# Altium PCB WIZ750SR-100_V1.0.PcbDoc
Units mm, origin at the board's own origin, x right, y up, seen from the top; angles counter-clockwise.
Board outline 50 x 30 mm, 4 copper layers (Top Layer, Internal Plane 1, Internal Plane 2, Bottom Layer); 73 components, 80 nets, 307 pads, 130 vias.
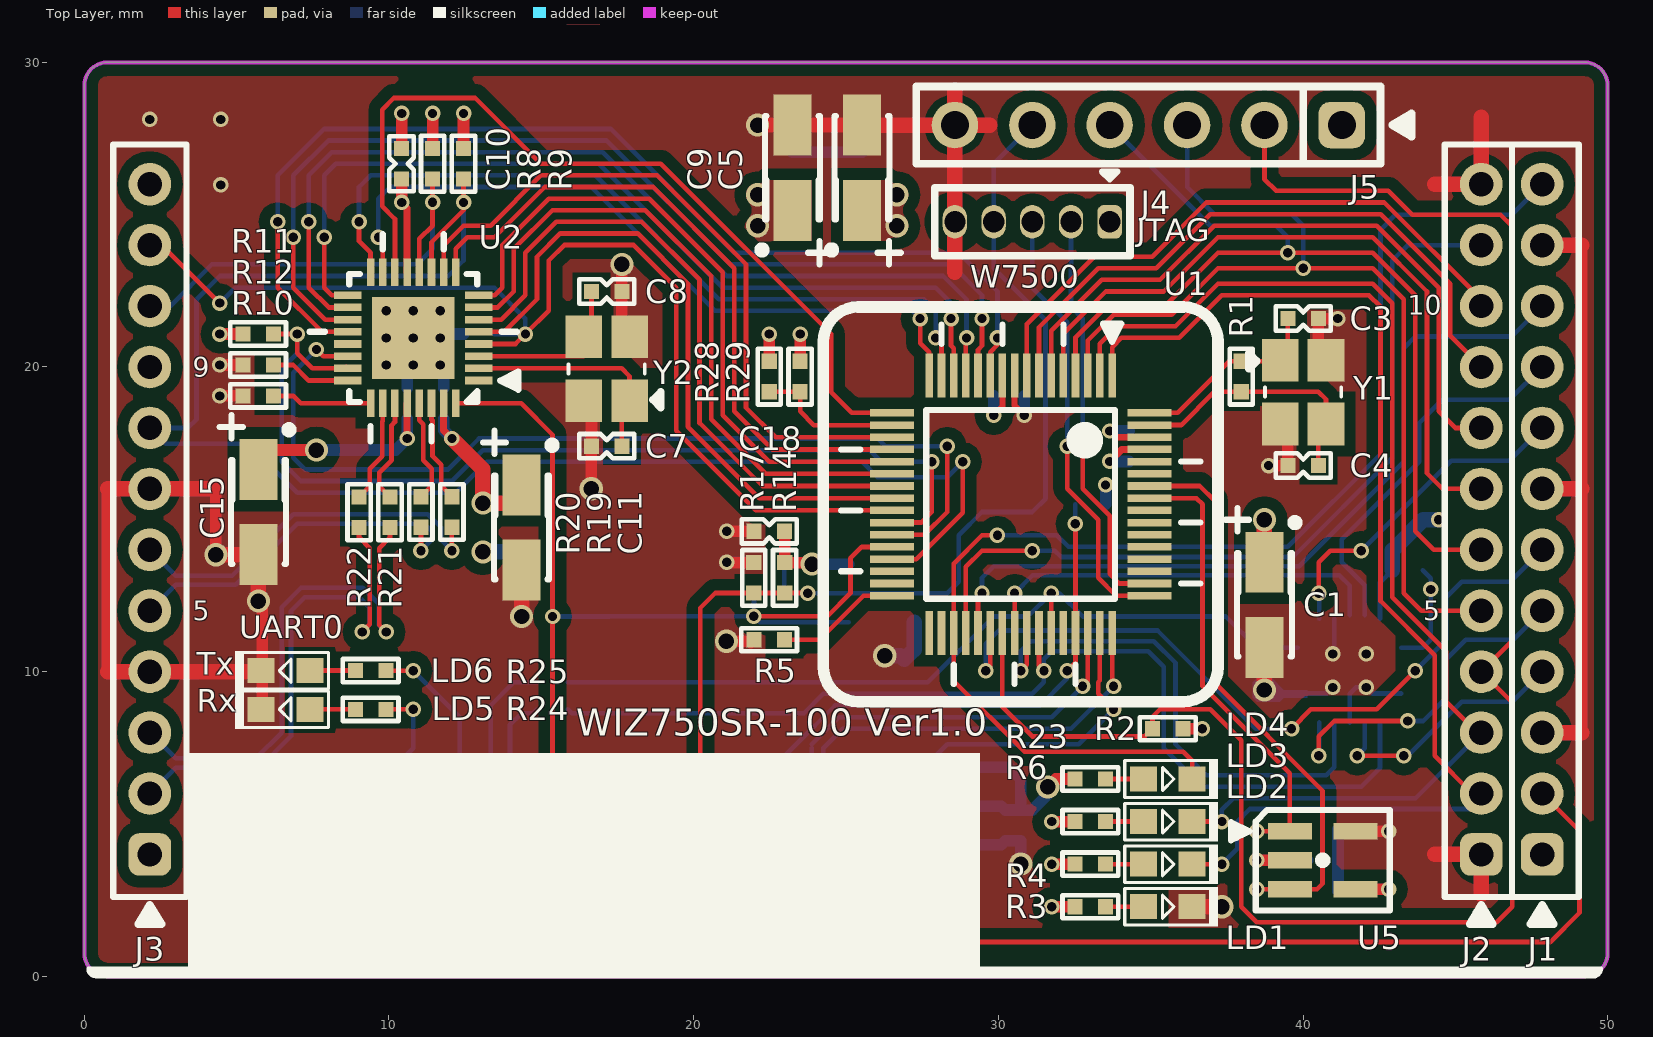
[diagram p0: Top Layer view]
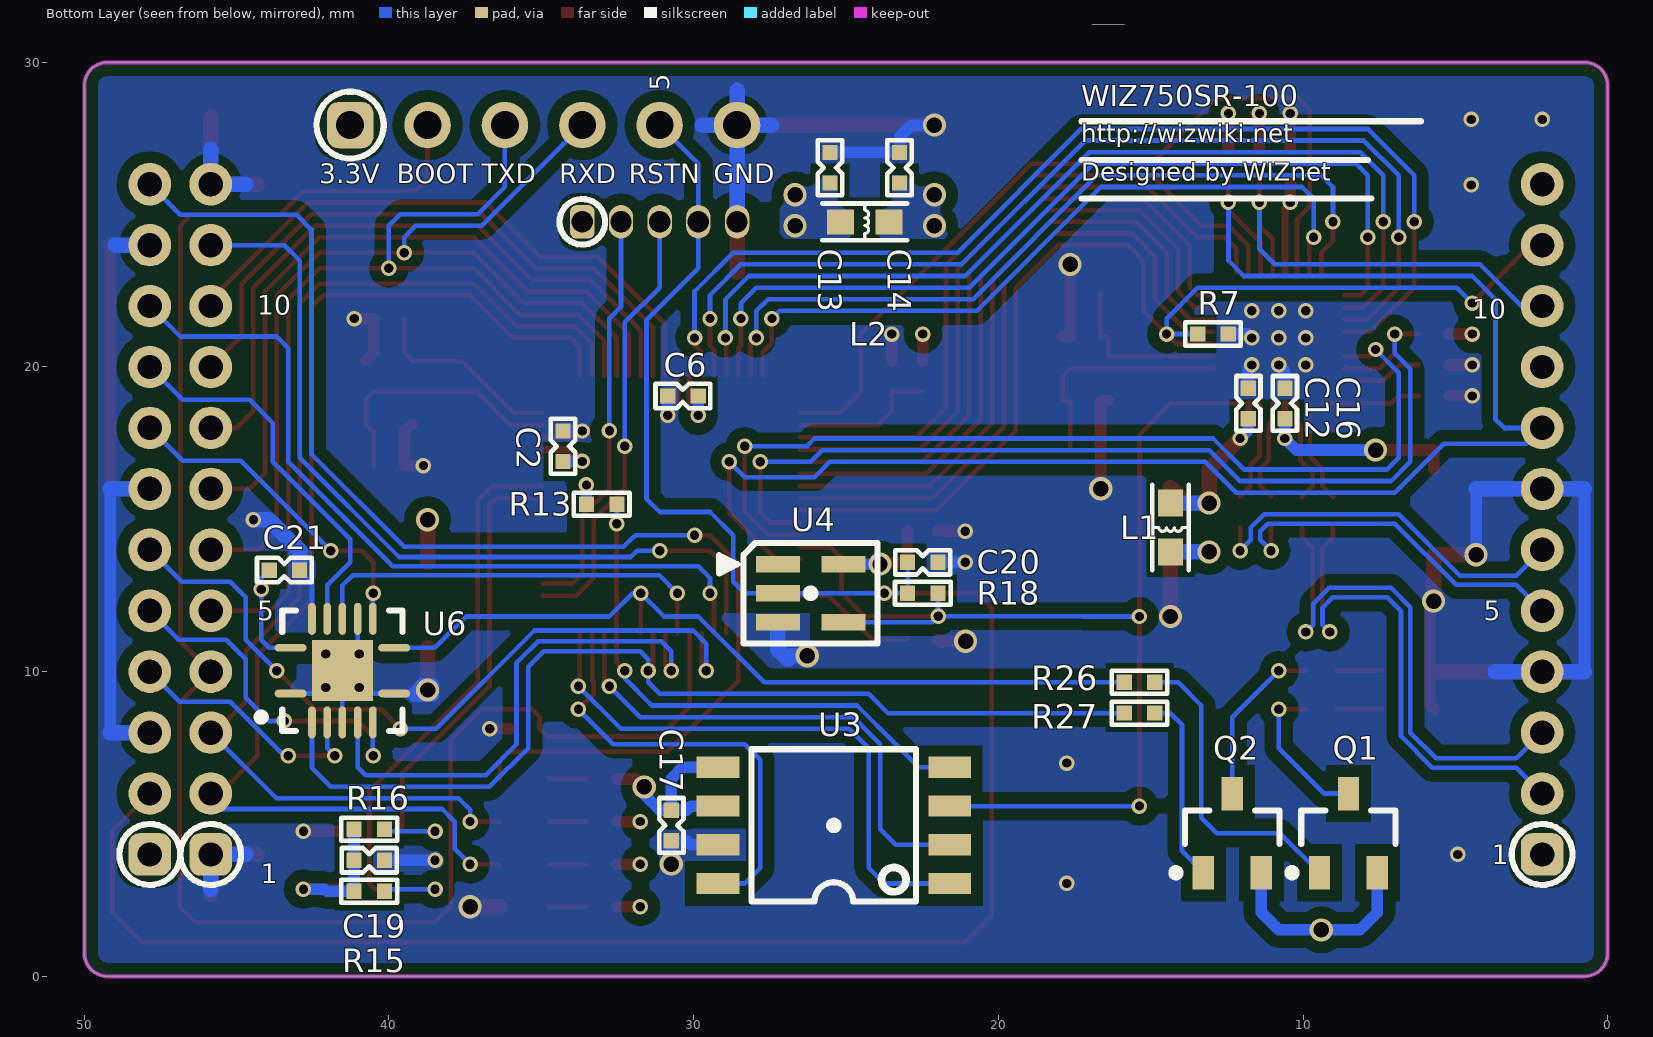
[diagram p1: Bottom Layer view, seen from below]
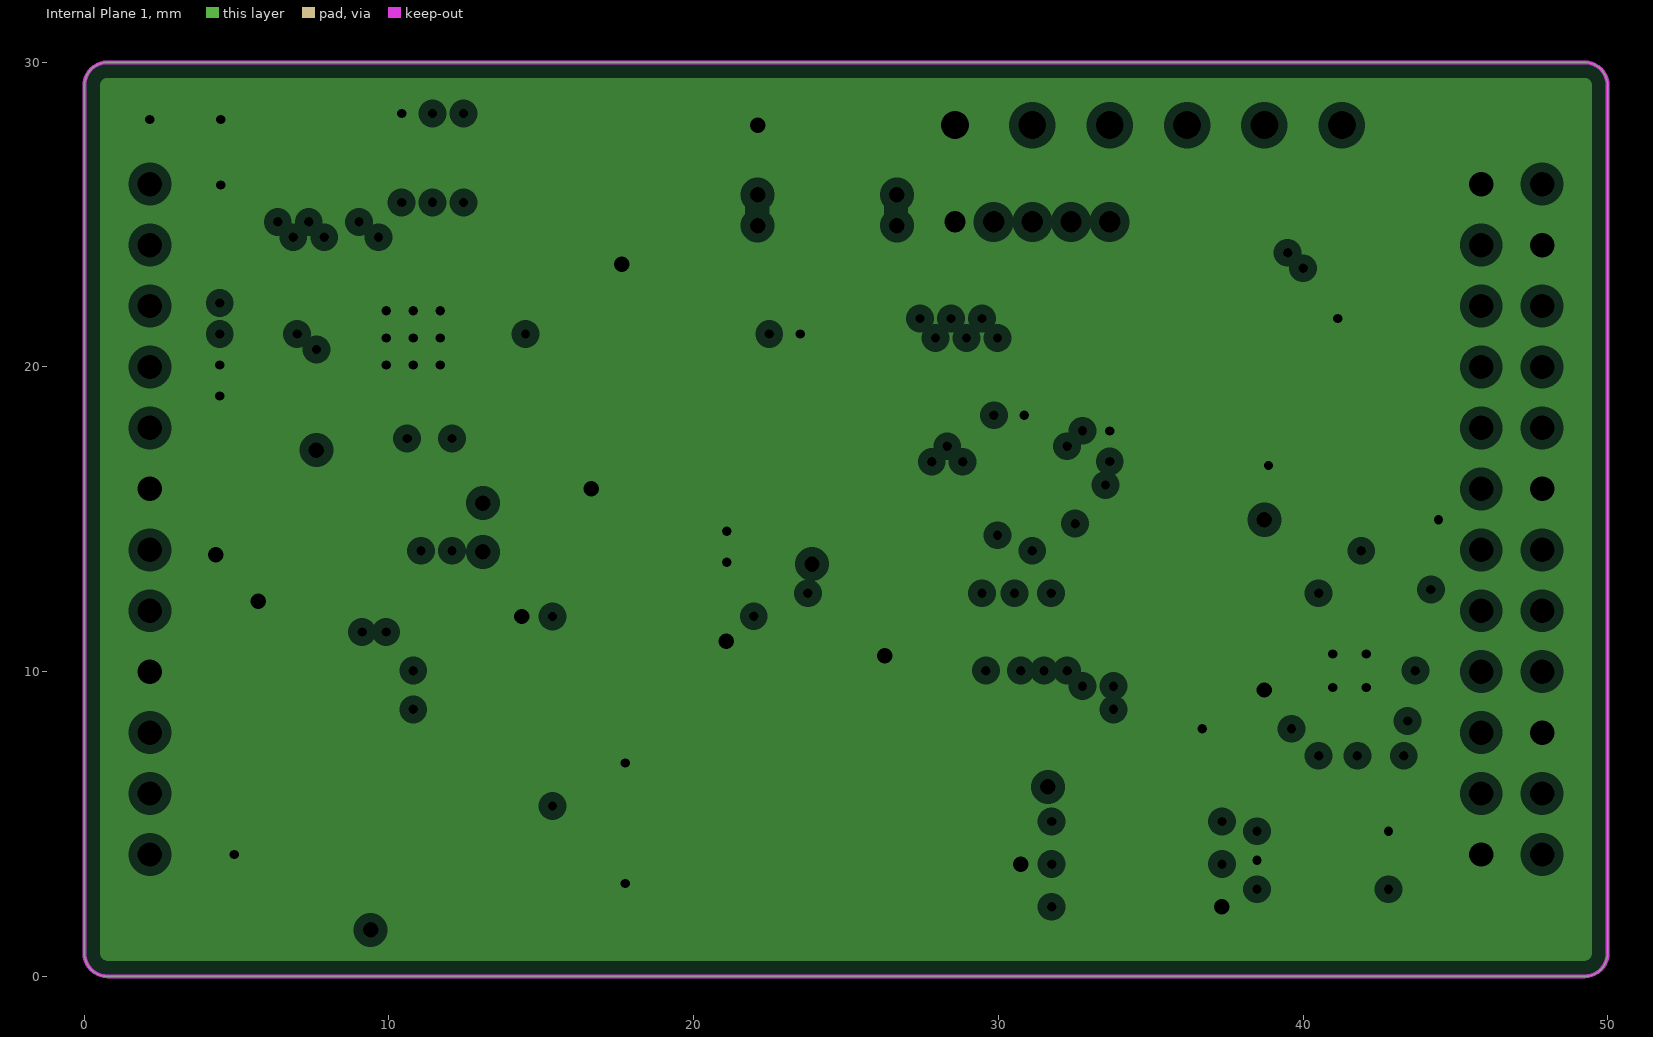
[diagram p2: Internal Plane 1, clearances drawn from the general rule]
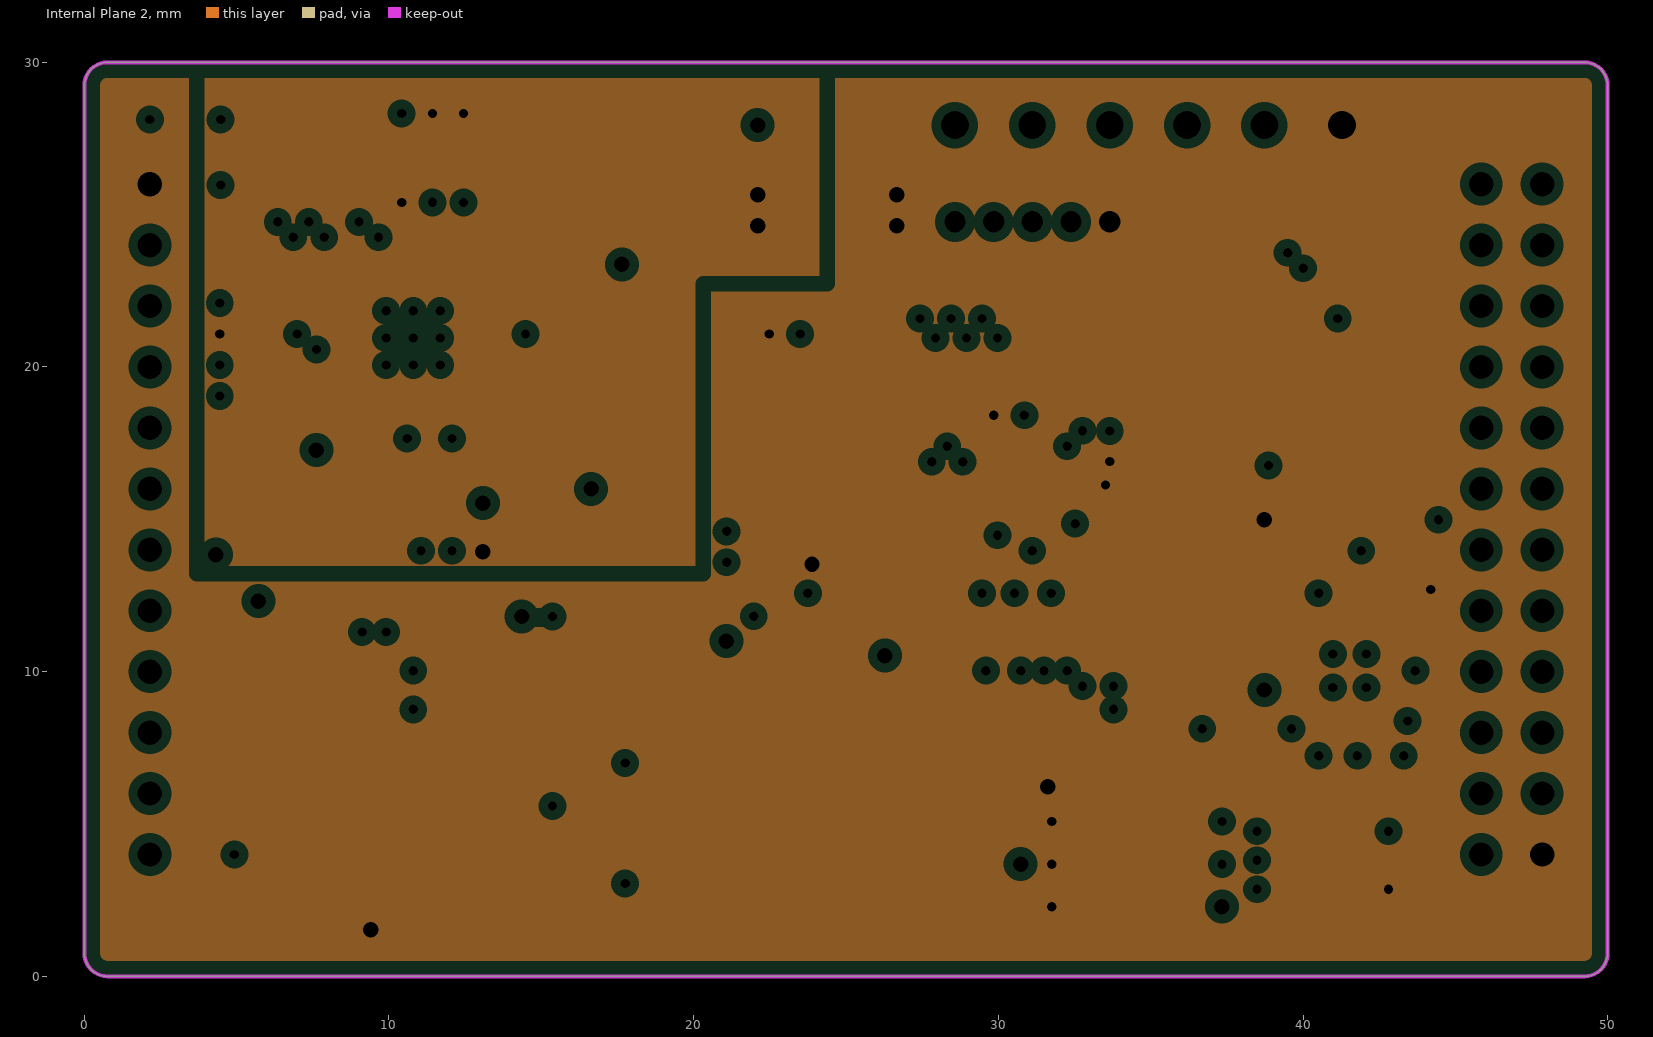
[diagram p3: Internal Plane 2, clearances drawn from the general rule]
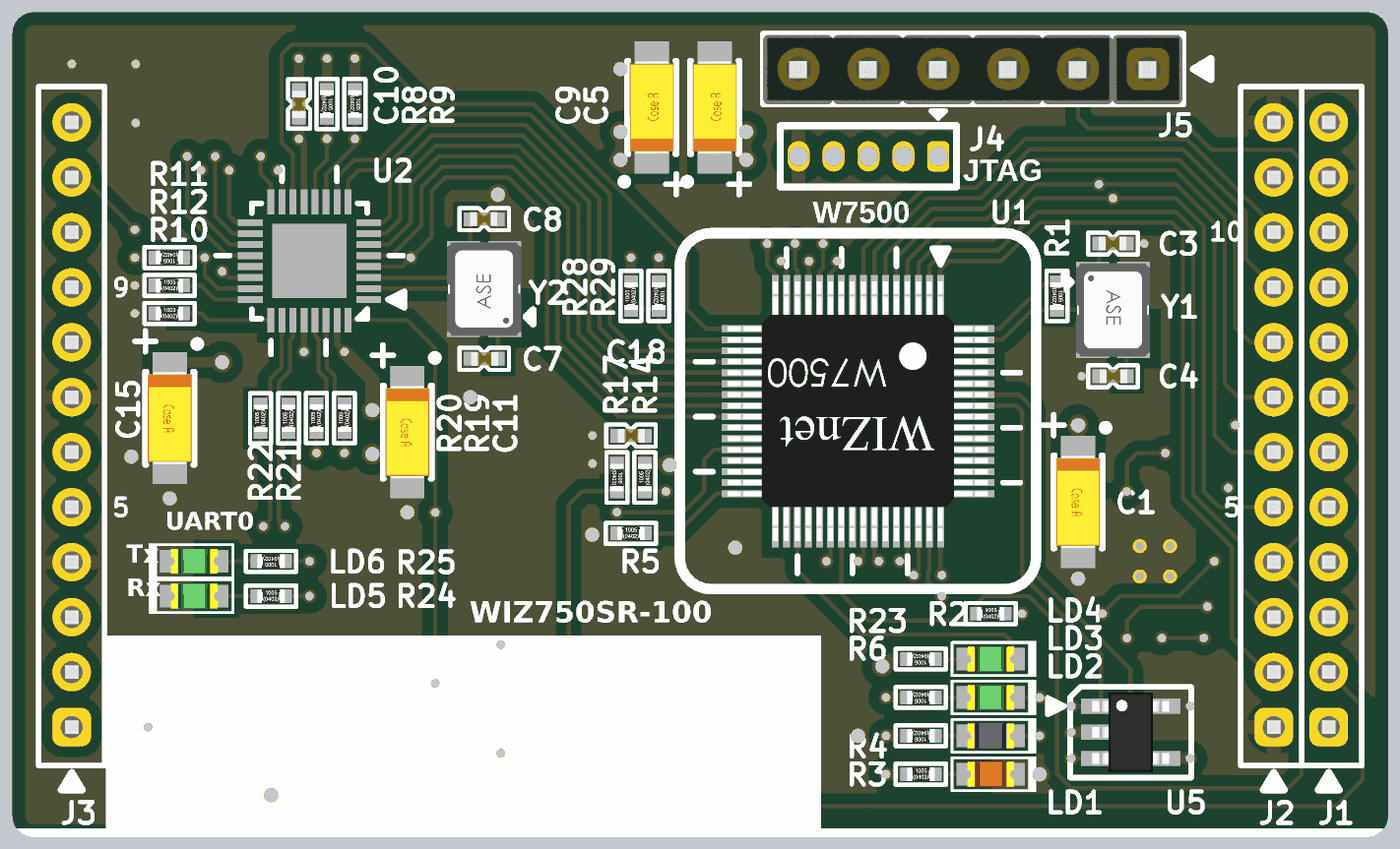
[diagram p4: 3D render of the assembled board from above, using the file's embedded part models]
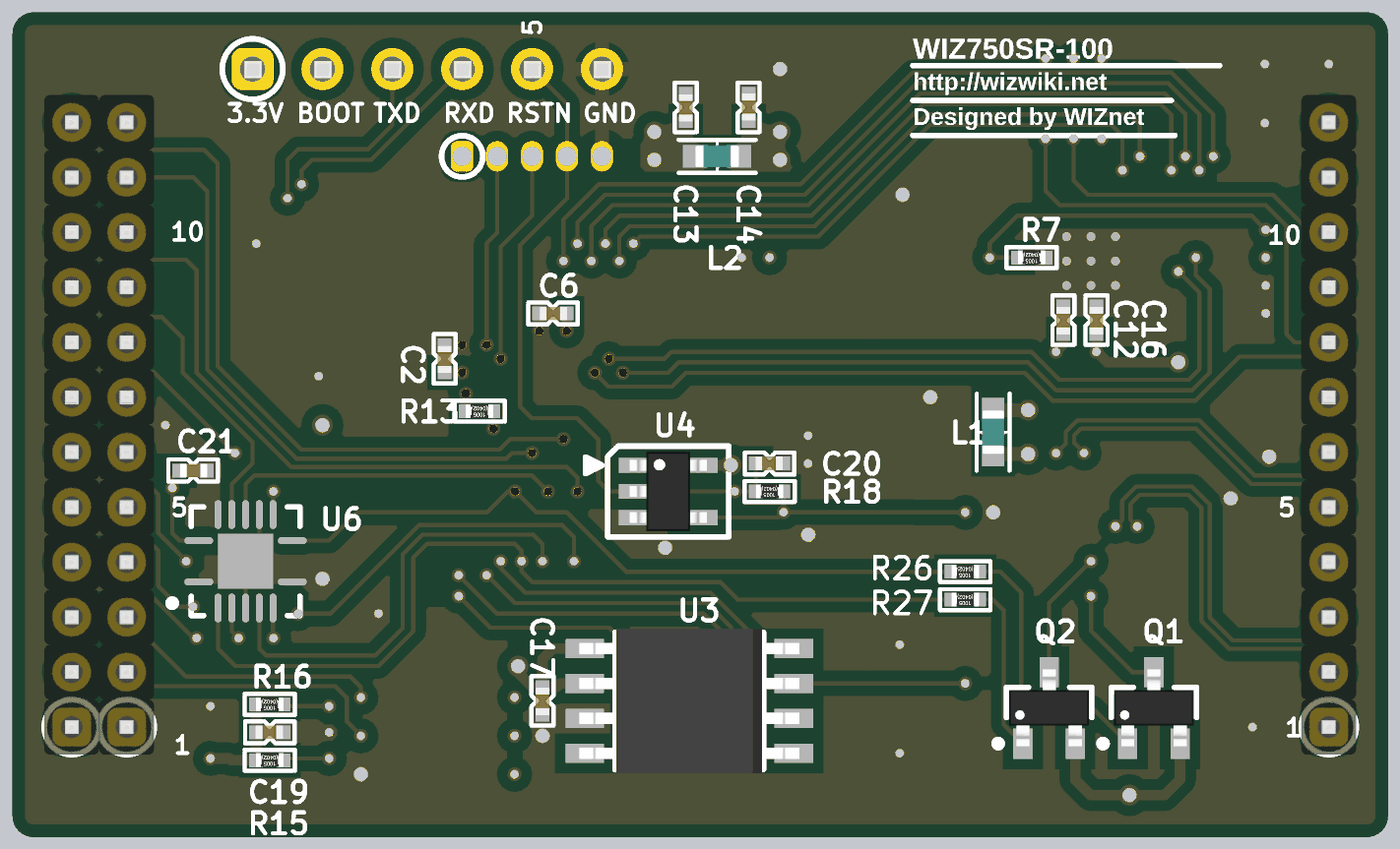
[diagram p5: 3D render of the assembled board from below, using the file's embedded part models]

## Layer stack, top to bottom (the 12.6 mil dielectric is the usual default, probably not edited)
Top Solder: solder mask 0.0102, Solder Resist, Dk 3.5
Top Layer: signal copper 0.0356
Dielectric1: core 0.32, FR-4, Dk 4.8
Internal Plane 1: plane copper 0.0356, net GND
Dielectric5: prepreg 0.32, FR-4, Dk 4.8
Internal Plane 2: plane copper 0.0356, net (Multiple Nets)
Dielectric6: core 0.32, FR-4, Dk 4.8
Bottom Layer: signal copper 0.0356
Bottom Solder: solder mask 0.0102, Solder Resist, Dk 3.5

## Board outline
0,0.762 0,29.238 cw(c0.762,29.238) 0.762,30 49.238,30 cw(c49.238,29.238) 50,29.238 50,0.762 cw(c49.238,0.762) 49.238,0 0.762,0 cw(c0.762,0.762)

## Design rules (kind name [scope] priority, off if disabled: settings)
Clearance [All] p1: gap=0.15 except(0.381: Arc-Poly Track-Poly SMDPad-Poly THPad-Poly Via-Poly Fill-Poly Poly-Poly Poly-Region)
DiffPairsRouting [All] p1: maxlimit=0.152 minlimit=0.152 mostfreqgap=0.152 toplayer_minwidth=0.152 toplayer_maxwidth=0.152 toplayer_prefwidth=0.152 bottomlayer_minwidth=0.152 bottomlayer_maxwidth=0.152 bottomlayer_prefwidth=0.152 maxuncoupledlength=15.24
HoleSize [All] p1: absolutevalues=TRUE maxlimit=4.064 minlimit=0.025 maxpercent=80.000 minpercent=20.000
PlaneClearance [All] p1: clearance=0.305
PlaneConnect [All] p1: planeconnectstyle=Direct reliefexpansion=0.508 reliefentries=4 reliefconductorwidth=0.254 reliefairgap=0.254
PolygonConnect PolygonConnect_2 [IsPad vs IsNamedPolygon('Top Layer-GND') Or  IsNamedPolygon('Bottom Layer-GND')] p1: connectstyle=Relief reliefconductorwidth=0.381 reliefentries=4 polygonreliefangle="90 Angle" airgapwidth=0.381
PolygonConnect PolygonConnect_1 [IsVia] p2: connectstyle=Direct reliefconductorwidth=0.254 reliefentries=4 polygonreliefangle="90 Angle" airgapwidth=0.254
PolygonConnect [All] p3: connectstyle=Direct reliefconductorwidth=0.254 reliefentries=4 polygonreliefangle="90 Angle" airgapwidth=0.254
RoutingVias [All] p1: holewidth=0.305 width=0.508 viastyle="Through Hole" minholewidth=0.305 minwidth=0.508 maxholewidth=0.508 maxwidth=0.762
SolderMaskExpansion [All] p1: expansion=0
Width [All] p1: maxlimit=0.508 minlimit=0.102 preferedwidth=0.152 minimp=50.000000 maximp=50.000000 favimp=50.000000
26 further rules are at their usual default settings.

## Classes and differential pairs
component class 2.WIZ750SR_Transceiver: LD1 LD2 R41
component class 1.WIZ750JR_W7500_: C1 C2 C3 C4 C5 C6 LD1 LD2 LD3 LD4 LD5 LD6 Q1 Q2 R1 R2 R3 R4 R5 R6 R23 R24 R25 R26 R27 R28 R29 U1 Y1
differential pair MDI0_T: +MDI0_T_P -MDI0_T_N
differential pair MDI0_R: +MDI0_R_P -MDI0_R_N
differential pair MDI0_R: +MDI_R_P -MDI_R_N
differential pair MDI0_T: +MDI_T_P -MDI_T_N

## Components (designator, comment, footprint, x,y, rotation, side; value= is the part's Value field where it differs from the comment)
C1 "10uF/16V" "CAP-A Size" 38.735,12.192 r270 top
C2 "1uF" CAP-0402#1 34.29,17.399 r270 bottom
C3 "30pF" CAP-0402#1 40.005,21.59 r180 top
C4 "30pF" CAP-0402#1 40.005,16.764 r0 top
C5 "10uF/16V" "CAP-A Size" 25.527,26.543 r90 top
C6 "1uF" CAP-0402#1 30.353,19.05 r180 bottom
C7 "27pF" CAP-0402#1 17.145,17.399 r0 top
C8 "27pF" CAP-0402#1 17.145,22.479 r180 top
C9 "10uF/16V" "CAP-A Size" 23.241,26.543 r90 top
C10 "0.1uF" CAP-0402#1 10.414,26.67 r270 top
C11 "10uF/16V" "CAP-A Size" 14.351,14.732 r270 top
C12 "0.1uF" CAP-0402#1 11.795,18.805 r270 bottom
C13 "0.1uF" CAP-0402#1 25.527,26.543 r270 bottom
C14 "0.1uF" CAP-0402#1 23.241,26.543 r90 bottom
C15 "10uF/16V" "CAP-A Size" 5.715,15.24 r270 top
C16 "0.1uF" CAP-0402#1 10.595,18.805 r270 bottom
C17 "0.1uF(NM)" CAP-0402#1 30.734,4.953 r270 bottom
C18 "0.1uF" CAP-0402#1 22.479,14.605 r0 top
C19 "0.1uF(NM)" CAP-0402#1 40.648,3.81 r0 bottom
C20 "0.1uF" CAP-0402#1 22.479,13.589 r0 bottom
C21 "0.1uF" CAP-0402#2 43.434,13.335 r180 bottom
J1 "2.00mm 1x12 Pin" IDC-1X12(2MM) 47.85,4 r90 top locked
J2 "2.00mm 1x12 Pin(NM)" IDC-1X12(2MM) 45.85,4 r90 top locked
J3 "2.00mm 1x12 Pin" IDC-1X12(2MM) 2.15,4 r90 top locked
J4 "1.27mm_1x5_Pin_header_DIP(NM)" IDC-1X5(1.27MM) 33.655,24.765 r180 top
J5 "2.54mm 1x6 Pin Header DIP(NM)" IDC-1X6 41.275,27.94 r180 top locked
L1 "HH-1M1608-121JT" IND-0603 14.351,14.732 r270 bottom
L2 "HH-1M1608-121JT" IND-0603 24.384,24.765 r180 bottom
LD1 "RED-0603" LED-0603-RED 35.56,2.286 r0 top
LD2 "BLUE-0603" LED-0603-BLUE 35.56,3.683 r0 top
LD3 "GREEN-0603" LED-0603-GREEN 35.56,5.08 r0 top
LD4 "GREEN-0603" LED-0603-GREEN 35.56,6.477 r0 top
LD5 "GREEN-0603" LED-0603-GREEN 6.604,8.763 r180 top
LD6 "GREEN-0603" LED-0603-GREEN 6.604,10.033 r180 top
Q1 "Q-MMBT4403" Q-MMBT4403-SOT23 8.509,4.699 r90 bottom
Q2 "Q-MMBT4403" Q-MMBT4403-SOT23 12.319,4.699 r90 bottom
R1 "1M" RES-0402#1 37.973,19.685 r270 top
R2 "4.7K" RES-0402#1 35.56,8.128 r0 top
R3 "330R" RES-0402#1 33.02,2.286 r0 top
R4 "1K" RES-0402#1 33.02,3.683 r180 top
R5 "4.7K" RES-0402#1 22.479,11.049 r0 top
R6 "330R" RES-0402#1 33.02,5.08 r180 top
R7 "5.1K" RES-0402#1 12.954,21.082 r0 bottom
R8 "5.1K" RES-0402#1 11.43,26.67 r270 top
R9 "5.1K" RES-0402#1 12.446,26.67 r270 top
R10 "6.19K / 1%" RES-0402#1 5.707,19.05 r0 top
R11 "5.1K" RES-0402#1 5.707,21.082 r180 top
R12 "5.1K" RES-0402#1 5.707,20.066 r0 top
R13 "4.7K(NM)" RES-0402#1 33.02,15.494 r0 bottom
R14 "4.7K(NM)" RES-0402#1 22.987,13.081 r90 top
R15 "4.7K(NM)" RES-0402#1 40.648,2.794 r0 bottom
R16 "4.7K(NM)" RES-0402#1 40.648,4.826 r0 bottom
R17 "4.7K" RES-0402#1 21.971,13.081 r270 top
R18 "0R(NM)" RES-0402#1 22.479,12.573 r0 bottom
R19 "3.3R" RES-0402#1 12.065,15.24 r90 top
R20 "3.3R" RES-0402#1 11.049,15.24 r90 top
R21 "3.3R" RES-0402#1 10.033,15.232 r90 top
R22 "3.3R" RES-0402#1 9.017,15.232 r90 top
R23 "330R" RES-0402#1 33.02,6.477 r180 top
R24 "330R" RES-0402#2 9.398,8.763 r0 top
R25 "330R" RES-0402#2 9.398,10.033 r180 top
R26 "1K" RES-0402#2 15.367,9.652 r0 bottom
R27 "1K" RES-0402#2 15.367,8.636 r0 bottom
R28 "4.7K/NC" RES-0402#2 22.479,19.685 r90 top
R29 "4.7K" RES-0402#2 23.495,19.685 r270 top
U1 "W7500" W7500-LQFP64 30.734,15.494 r270 top locked
U2 "IP101GR/GRI" QFN32(0.4/4X4) 10.795,20.955 r180 top locked
U3 "AT45DB161E-SHF-T" SO-08-EIAJ 25.4,4.953 r0 bottom
U4 "SN74LVC1G04DBVR" SOT-23-5L 26.162,12.573 r180 bottom
U5 "24AA16T-I/OT" SOT-23-5L 40.648,3.81 r0 top
U6 "SN74LVC125A" SN74LVC125A 41.529,10.033 r180 bottom
Y1 "12MHz" OSC-TZ1067B 40.005,19.177 r270 top
Y2 "25MHz" OSC-82J0626 17.145,19.939 r90 top

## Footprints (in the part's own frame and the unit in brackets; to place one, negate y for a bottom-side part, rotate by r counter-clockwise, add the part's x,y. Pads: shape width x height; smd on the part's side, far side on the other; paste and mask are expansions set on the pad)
CAP-0402#1 [mm]
  rect 0.5x0.5 smd: 1(-0.5,0) 2(0.5,0)
  silkscreen extent -0.9,-0.4 0.9,0.4, body extent -0.48,-0.25 0.52,0.25, height 0.6
CAP-0402#2 [mm] "Ceramic CAP 0402(1005)"
  rect 0.5x0.5 smd: 1(-0.5,-0.004) 2(0.5,-0.004)
  silkscreen extent -0.9,-0.4 0.9,0.4, body extent -0.48,-0.25 0.52,0.25, height 0.6
"CAP-A Size" [mm] "Tantal CAP A Size EIA/IECQ 3216"
  rect 2x1.25 smd: 1(-1.4,0) 2(1.4,0)
  silkscreen extent -3.17,-1.27 1.7,1.12, body extent -1.7,-0.8 1.7,0.8, height 1.75
IDC-1X5(1.27MM) [mm]
  rrect50% 0.8x1.1 hole 0.7: 1(0,0)
  oval 0.8x1.1 hole 0.7: 2(1.27,0) 3(2.54,0) 4(3.81,0) 5(5.08,0)
  silkscreen extent -0.66,-1.65 5.74,1.11
IDC-1X6 [mil] "6-Way 2.54 mm Male Header"
  rrect50% 60x60 hole 36: 1(0,0)
  round 60 hole 36: 2(100,0) 3(200,0) 4(300,0) 5(400,0) 6(500,0)
  silkscreen extent -90,-50 550,50, body extent -49,-49 551,51, height 336
IDC-1X12(2MM) [mil]
  rrect50% 55x55 hole 31.5: 1(0,0)
  round 55 hole 31.5: 2(78.74,0) 3(157.48,0) 4(236.22,0) 5(314.96,0) 6(393.7,0) 7(472.44,0) 8(551.18,0) 9(629.92,0) 10(708.66,0) 11(787.4,0) 12(866.14,0)
  silkscreen extent -90,-47 917,39, body extent -39,-39 906,39, height 217
IND-0603 [mm] "Inductor 0603(1608)"
  rect 0.89x0.82 smd: 1(-0.8,0) 2(0.8,0)
  silkscreen extent -1.4,-0.6 1.4,0.6, body extent -0.8,-0.4 0.8,0.4, height 0.95
LED-0603-BLUE [mm] "LED-0603-BLUE"
  rect 0.89x0.82 smd: 1(-0.8,0) 2(0.8,0)
  silkscreen extent -1.41,-0.65 1.65,0.65, body extent -0.85,-0.45 0.85,0.45, height 0.9
LED-0603-GREEN [mm] "LED-0603-GREEN"
  rect 0.89x0.82 smd: 1(-0.8,0) 2(0.8,0)
  silkscreen extent -1.41,-0.65 1.65,0.65, body extent -0.85,-0.45 0.85,0.45, height 0.9
LED-0603-RED [mm] "LED-0603-RED"
  rect 0.89x0.82 smd: 1(-0.8,0) 2(0.8,0)
  silkscreen extent -1.41,-0.65 1.65,0.65, body extent -0.85,-0.45 0.85,0.45, height 0.9
OSC-82J0626 [mm]
  rect 1.4x1.2 smd: 1(-1.05,-0.75) 2(1.05,-0.75) 3(1.05,0.75) 4(-1.05,0.75)
  silkscreen extent -1.27,-1.78 0.15,1.25, body extent -1.7,-1.35 1.7,1.35, height 1.06
OSC-TZ1067B [mm]
  rect 1.4x1.2 smd: 1(-1.05,-0.75) 2(1.05,-0.75) 3(1.05,0.75) 4(-1.05,0.75)
  silkscreen extent -1.27,-1.78 0.15,1.25, body extent -1.7,-1.35 1.7,1.35, height 1.06
Q-MMBT4403-SOT23 [mm] "PNP General-Purpose Amplifier"
  rect 1.1x0.7 smd: 1(-1.3,0.95) 2(-1.3,-0.95) 3(1.3,0)
  silkscreen extent -1.42,-1.55 0.75,1.98, body extent -1.4,-1.45 1.4,1.45, height 1.3
QFN32(0.4/4X4) [mm]
  rect 0.9x0.25 smd: 1(-2.15,1.4) 2(-2.15,1) 3(-2.15,0.6) 4(-2.15,0.2) 5(-2.15,-0.2) 6(-2.15,-0.6) 7(-2.15,-1) 8(-2.15,-1.4) 17(2.15,-1.4) 18(2.15,-1) 19(2.15,-0.6) 20(2.15,-0.2) 21(2.15,0.2) 22(2.15,0.6) 23(2.15,1) 24(2.15,1.4)
  rect 0.25x0.9 smd: 9(-1.4,-2.15) 10(-1,-2.15) 11(-0.6,-2.15) 12(-0.2,-2.15) 13(0.2,-2.15) 14(0.6,-2.15) 15(1,-2.15) 16(1.4,-2.15) 25(1.4,2.15) 26(1,2.15) 27(0.6,2.15) 28(0.2,2.15) 29(-0.2,2.15) 30(-0.6,2.15) 31(-1,2.15) 32(-1.4,2.15)
  rect 2.7x2.7 smd: 33(0,0)
  silkscreen extent -3.45,-3.4 3.4,3.4, body extent -2.1,-2.1 2.1,2.1, height 0.76
RES-0402#1 [mm]
  rect 0.5x0.5 smd: 1(-0.5,0) 2(0.5,0)
  silkscreen extent -0.91,-0.38 0.91,0.38, body extent -0.5,-0.25 0.5,0.25, height 0.35
RES-0402#2 [mm]
  rect 0.5x0.5 smd: 1(-0.5,-0.004) 2(0.5,-0.004)
  silkscreen extent -0.91,-0.38 0.91,0.38, body extent -0.5,-0.25 0.5,0.25, height 0.35
SN74LVC125A [mm] "QFN, 14-Leads, Body 3.50x3.50mm, Pitch 0.50mm/1.50mm, Thermal Pad 2.00x2.00mm, IPC Low Density"
  oval 1.05x0.25 smd: 1(-1.7,-0.75) 7(1.7,-0.75) 8(1.7,0.75) 14(-1.7,0.75)
  oval 0.25x1.05 smd: 2(-1,-1.7) 3(-0.5,-1.7) 4(0,-1.7) 5(0.5,-1.7) 6(1,-1.7) 9(1,1.7) 10(0.5,1.7) 11(0,1.7) 12(-0.5,1.7) 13(-1,1.7)
  rect 2x2 smd: 15(0,0)
  silkscreen extent -2.79,-1.97 1.97,1.97, body extent -1.83,-1.83 1.83,1.83, height 1
SO-08-EIAJ [mm]
  rect 1.4x0.7 smd: 1(-3.8,1.905) 2(-3.8,0.635) 3(-3.8,-0.635) 4(-3.8,-1.905) 5(3.8,-1.905) 6(3.8,-0.635) 7(3.8,0.635) 8(3.8,1.905)
  silkscreen extent -2.7,-2.5 2.7,2.5, body extent -4,-2.63 4,2.63, height 2.58
SOT-23-5L [mm]
  rect 1.45x0.55 smd: 1(-1.075,0.95) 2(-1.075,0) 3(-1.075,-0.95) 4(1.075,-0.95) 5(1.075,0.95)
  silkscreen extent -3.01,-1.65 2.2,1.65, body extent -1.4,-1.45 1.4,1.45, height 1.45
W7500-LQFP64 [mm] "WIZnet ARM Cortex-M0, LQFP64, Pitch 0.40mm"
  rect 1.45x0.25 smd: 1(-4.225,3) 2(-4.225,2.6) 3(-4.225,2.2) 4(-4.225,1.8) 5(-4.225,1.4) 6(-4.225,1) 7(-4.225,0.6) 8(-4.225,0.2) 9(-4.225,-0.2) 10(-4.225,-0.6) 11(-4.225,-1) 12(-4.225,-1.4) 13(-4.225,-1.8) 14(-4.225,-2.2) 15(-4.225,-2.6) 16(-4.225,-3) 33(4.225,-3) 34(4.225,-2.6) 35(4.225,-2.2) 36(4.225,-1.8) 37(4.225,-1.4) 38(4.225,-1) 39(4.225,-0.6) 40(4.225,-0.2) 41(4.225,0.2) 42(4.225,0.6) 43(4.225,1) 44(4.225,1.4) 45(4.225,1.8) 46(4.225,2.2) 47(4.225,2.6) 48(4.225,3)
  rect 0.25x1.45 smd: 17(-3,-4.225) 18(-2.6,-4.225) 19(-2.2,-4.225) 20(-1.8,-4.225) 21(-1.4,-4.225) 22(-1,-4.225) 23(-0.6,-4.225) 24(-0.2,-4.225) 25(0.2,-4.225) 26(0.6,-4.225) 27(1,-4.225) 28(1.4,-4.225) 29(1.8,-4.225) 30(2.2,-4.225) 31(2.6,-4.225) 32(3,-4.225) 49(3,4.225) 50(2.6,4.225) 51(2.2,4.225) 52(1.8,4.225) 53(1.4,4.225) 54(1,4.225) 55(0.6,4.225) 56(0.2,4.225) 57(-0.2,4.225) 58(-0.6,4.225) 59(-1,4.225) 60(-1.4,4.225) 61(-1.8,4.225) 62(-2.2,4.225) 63(-2.6,4.225) 64(-3,4.225)
  silkscreen extent -6.48,-6.48 6.48,6.48, body extent -4.73,-4.74 4.73,4.72, height 1

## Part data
C1 C5 C9 C11 C15: library part "CAP-A Size", "Tantla CAP A Size EIA/IECQ 3216"
C2 C3 C4 C6 C7 C8 C10 C12 C13 C14 C16 C17 C18 C19 C20 C21: library part CAP-0402, "Ceramic CAP 0402(1005)"
J1 J2 J3: library part "Header 1x12 (2.00mm)", "pin header 2.00mm 1x12"
J4: library part 1.27mm_1x5_Pin_header_DIP, "1.27mm_1x5_Pin_header_DIP"
J5: library part "Header 6", "Header, 6-Pin"
L1 L2: library part IND-0603, "Inductor 0603(1608)"
LD1 LD2 LD3 LD4 LD5 LD6: library part LED-0603, "LED-0603"
Q1 Q2: "PNP General-Purpose Amplifier"
R1 R2 R3 R4 R5 R6 R7 R10 R11 R12 R13 R14 R15 R16 R17 R18 R19 R20 R21 R22 R23 R24 R25 R26 R27 R28 R29: library part RES-0402, "RES-0402"
R8 R9: library part RES-0603, "RES-0402"
U1: "WIZnet ARM Cortex-M0"
U3: "16-Mbit DataFlash, 2.3V or 2.5V Minimum SPI Serial Flash Memory"
U4: "IC, INVERTER, SINGLE, SMD, SOT-23-5"
U5: library part 24AAxxT-i-OT, "SOT-23"
U6: "Quadruple Bus Buffer Gate With 3-State Outputs"
Y1: library part OSC-TZ1067B-12MHz, "X-tal 12MHz,3.2x2.5 SMD, CL=20pF"
Y2: library part OSC-82J0626-25MHz, "X-tal 25MHz,3.2x2.5 SMD, CL=18pF"

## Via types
v1: diameter 0.508, hole 0.305, Top Layer to Bottom Layer, tented both sides, 104 vias
v2: diameter 0.762, hole 0.508, Top Layer to Bottom Layer, tented both sides, 22 vias
v3: diameter 0.508, hole 0.305, Top Layer to Bottom Layer, 4 vias

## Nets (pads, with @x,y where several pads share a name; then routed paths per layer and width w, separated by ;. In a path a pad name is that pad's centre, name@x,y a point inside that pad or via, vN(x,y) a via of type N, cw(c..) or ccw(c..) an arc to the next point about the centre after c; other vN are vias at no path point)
APP_BOOT: J2.11 U1.36 | length 27.4
  Top Layer w0.152: U1.36 28.934,13.44 29.464,13.97 v1(31.115,13.97)
  Bottom Layer w0.152: v1(31.115,13.97) 31.855,13.97 32.061,13.764 32.333,13.764 39.672,13.764 42.926,17.018 42.926,23.495 43.431,24 J2.11
BOOT: J2.4 J5.2 R2.1 U1.39 | length 60.2
  Top Layer w0.152: U1.39 30.134,8.855 31.115,7.874 34.806,7.874 R2.1 35.06,8.517 35.306,8.763 36.957,8.763 37.973,7.747 37.973,2.286 38.481,1.778 46.355,1.778 46.863,2.286 46.863,8.987 J2.4 46.85,11 46.85,24.632 46.482,25 43.58,25 42.799,25.781 39.116,25.781 38.735,26.162 J5.2
DUP: R28.1 R29.2 U1.18 | length 4.9
  Top Layer w0.152: R28.1 23.495,19.185 23.495,18.542 23.943,18.094 U1.18
EX_RESET: C20.2 J1.2 J4.4 J5.5 R14.1 R17.2 R18.2 U4.2 | length 73.1
  Top Layer w0.152: v1(23.749,12.573) 23.741,12.581 R14.1 R17.2 20.709,12.581 20.218,12.09 20.218,2.007 21.1,1.125 48.115,1.125 49.075,2.085 49.075,4.775 J1.2
  Bottom Layer w0.152: C20.2 R18.2 v1(23.749,12.573) U4.2 28.321,12.573 28.702,12.954 28.702,14.478 29.464,15.24 31.115,15.24 31.55,15.675 31.55,21.536 29.845,23.241 J4.4 29.845,26.67 J5.5
EXPANSION_GPIO_A: J2.10 U1.8 | length 19.8
  Top Layer w0.152: U1.8 30.934,21.409 33.147,23.622 35.052,23.622 36.83,25.4 42.672,25.4 45.85,22.222 J2.10
EXPANSION_GPIO_B: J2.9 U1.7 | length 20.7
  Top Layer w0.152: U1.7 31.334,21.301 33.274,23.241 35.179,23.241 36.957,25.019 42.545,25.019 44.831,22.733 44.831,21.019 J2.9
EXPANSION_GPIO_C: J2.8 U1.6 | length 22.1
  Top Layer w0.152: U1.6 31.734,21.193 33.401,22.86 35.306,22.86 37.084,24.638 42.418,24.638 44.45,22.606 44.45,18.542 44.992,18 J2.8
EXPANSION_GPIO_D: J2.7 U1.5 | length 23.3
  Top Layer w0.152: U1.5 32.134,21.085 33.528,22.479 35.433,22.479 37.211,24.257 42.291,24.257 44.069,22.479 44.069,16.51 44.579,16 J2.7
GND: C1.2 C2.1 C3.1 C4.1 C5.2 C6.1 C7.1 C8.1 C9.2 C10.1 C11.2 C12.1 C13.1 C14.2 C15.2 C16.1 C17.2 C18.1 C19.1 C20.1 C21.2 J1.3 J1.7 J1.11 J2.1 J2.12 J3.4 J3.7 J4.5 J5.6 LD1.2 LD5.2 LD6.2 R2.2 R5.1 R7.1 R10.1 R12.1 R17.1 R29.1 U1.9 U1.62 U2.33 U3.7 U4.3 U5.2 U5.5 U6.1 U6.4 U6.7 U6.10 U6.13 U6.15 Y1.2 Y1.4 Y2.2 Y2.4 | length 151.8
  Top Layer w0.203: U1.9 30.534,18.734 v1(30.853,18.415)
  Top Layer w0.229: v1(33.655,17.899) 33.86,17.694 U1.62
  Top Layer w0.381: 0.762,10 0.762,16 ; v2(4.318,13.84) 4.318,16 ; v1(4.445,19.05) R10.1 ; v1(4.445,20.066) R12.1 ; LD5.2@5.677,8.763 5.842,8.928 5.842,12.192 v2(5.715,12.319) ; C10.1 v1(10.414,28.321) ; Y2.4 16.645,18.889 C7.1 16.637,17.391 v2(16.637,16.002) ; v2(17.645,23.368) C8.1 17.645,20.989 Y2.2 ; v2(21.075,11) 21.83,11 21.88,10.95 R5.1 ; v1(21.082,13.589) 21.09,13.581 R17.1 ; v1(21.082,14.605) C18.1 ; R29.1@23.495,20.185 v1(23.495,21.082) ; R2.2 v1(36.695,8.128) ; v1(38.489,3.81) U5.2 ; v1(38.87,16.764) C4.1 39.505,17.877 Y1.2 ; Y1.4 40.505,20.477 C3.1 v1(41.14,21.59) ; U5.5 v1(42.807,4.76) ; 49.149,8 49.149,16 49.149,24
  Top Layer w0.508: 0.762,10 J3.4 LD6.2@5.715,10 ; 0.762,16 J3.7 4.318,16 ; v2(4.318,13.84) C15.2 v2(5.715,12.319) ; v2(14.351,11.811) C11.2@14.351,13.84 ; v2(22.098,27.94) 21.971,27.94 21.974,27.943 C9.2 C5.2 ; C5.2@25.527,27.94 J5.6 ; 28.575,23.114 J4.5 J5.6 ; 28.575,29.083 J5.6 ; 29.718,27.94 J5.6 ; LD1.2 v2(37.338,2.286) ; v2(38.735,9.398) C1.2 ; 44.323,4 J2.1 45.85,2.7 ; 44.323,26 J2.12 45.85,28.194 ; J1.3 49.149,8 ; J1.7 49.149,16 ; J1.11 49.149,24
  Bottom Layer w0.152: U6.7 40.779,9.283 v3(40.979,9.483) ; v3(40.979,10.583) 41.029,10.633 U6.10 ; U6.4 41.529,9.271 41.741,9.483 v3(42.079,9.483) 42.279,9.283 U6.1 ; U6.13 42.529,12.926 C21.2
  Bottom Layer w0.381: 0.762,10 0.762,16 ; v2(4.318,13.84) 4.318,16 ; C16.1 10.595,19.866 v1(10.795,20.066) ; v1(11.684,20.066) 11.795,19.955 C12.1 ; v1(11.684,20.955) 11.811,21.082 R7.1 ; v1(21.082,13.589) C20.1 ; v2(22.098,27.94) 22.86,27.94 23.241,27.559 C14.2 C13.1 ; U3.7 30.099,4.318 30.234,4.453 C17.2 v2(30.734,3.683) ; v1(30.853,18.415) C6.1 ; v1(33.655,17.899) C2.1 ; v1(38.489,3.81) C19.1 ; 49.149,8 49.149,16
  Bottom Layer w0.508: 0.762,10 J3.4 3.683,10 ; 0.762,16 J3.7 4.318,16 ; v2(26.275,10.525) 26.785,10.525 26.91,10.4 27.237,10.727 U4.3 ; 27.432,27.94 J5.6 ; J4.5 J5.6 ; 28.575,29.083 J5.6 ; 29.718,27.94 J5.6 ; C21.2 42.934,13.978 43.942,14.986 v1(44.45,14.986) ; 44.707,4 J2.1 45.85,2.857 ; 44.707,26 J2.12 45.85,27.143 ; J1.3 49.149,8 ; J1.7 49.149,16 ; J1.11 48.993,24
  other v1: 17.75,3.05 4.925,4 17.75,7 9.906,20.066 9.906,20.955 10.795,20.955 9.906,21.844 10.795,21.844 11.684,21.844 4.475,25.975 2.15,28.125 4.475,28.125
  other v3: 42.079,10.583
IN_CTS: J1.9 U6.12 | length 12.5
  Bottom Layer w0.152: U6.12@42.029,11.86 42.029,12.835 41.275,13.589 41.275,14.351 43.815,16.891 43.815,18.161 44.577,18.923 45.466,18.923 45.467,18.924 46.774,18.924 J1.9
IN_RXD: J1.8 U6.9 | length 11
  Top Layer w0.152: v1(40.513,12.573) 40.513,13.589 40.894,13.97 v1(41.91,13.97)
  Bottom Layer w0.152: v1(40.513,12.573) 40.529,12.557 U6.9 ; v1(41.91,13.97) 44.864,16.924 46.774,16.924 J1.8
IP_3.3A: C11.1 C12.2 L1.1 U2.31 | length 7.3
  Top Layer w0.229: U2.31 11.795,17.923 v1(12.065,17.653)
  Top Layer w0.508: v1(12.065,17.653) 13.081,16.637 v2(13.081,15.532) 13.843,15.532 C11.1@14.351,16.04
  Bottom Layer w0.381: C12.2 11.795,17.923 v1(12.065,17.653)
  Bottom Layer w0.508: v2(13.081,15.532) L1.1
IP_3.3V: C9.1 C10.2 C14.1 L1.2 L2.2 R8.1 R9.1 R11.2 U2.13 | length 7.5
  Top Layer w0.229: v1(10.414,25.4) 10.595,25.219 U2.13
  Top Layer w0.381: v1(4.445,21.082) R11.2 ; v1(10.414,25.4) C10.2 ; R8.1 v1(11.43,28.321) ; R9.1 v1(12.446,28.321)
  Bottom Layer w0.508: v2(13.081,13.932) L1.2
  other v2: 22.098,24.638 22.098,25.654
MDI0_R_N: R22.2 U2.26 | length 3.4
  Top Layer w0.152: R22.2 9.373,16.088 9.373,16.662 9.779,17.068 9.779,18.211 9.795,18.227 U2.26
MDI0_R_P: R21.2 U2.27 | length 3.4
  Top Layer w0.152: R21.2 9.677,16.088 9.677,16.535 10.084,16.942 10.084,18.085 10.195,18.196 U2.27
MDI0_T_N: R20.2 U2.29 | length 3.4
  Top Layer w0.152: U2.29 10.995,18.248 11.125,18.118 11.125,16.942 11.405,16.662 11.405,16.096 R20.2
MDI0_T_P: R19.2 U2.30 | length 3.3
  Top Layer w0.152: U2.30 11.395,18.279 11.43,18.244 11.43,17.068 11.709,16.789 11.709,16.096 R19.2
MDI_R_N: J3.2 R22.1 | length 17
  Top Layer w0.152: R22.1 9.017,14.406 9.373,14.05 9.373,11.557 v1(9.119,11.303)
  Bottom Layer w0.152: J3.2 2.998,6.848 5.755,6.848 6.782,7.875 6.782,11.989 7.239,12.446 9.017,12.446 9.36,12.103 9.36,11.544 v1(9.119,11.303)
MDI_R_P: J3.3 R21.1 | length 17.5
  Top Layer w0.152: v1(9.906,11.303) 9.677,11.532 9.677,14.05 10.033,14.406 R21.1
  Bottom Layer w0.152: J3.3 2.998,7.152 5.628,7.152 6.477,8.001 6.477,12.115 7.113,12.751 9.143,12.751 9.665,12.229 9.665,11.544 v1(9.906,11.303)
MDI_T_N: J3.5 R20.1 | length 12.1
  Top Layer w0.152: v1(11.049,13.97) R20.1
  Bottom Layer w0.152: J3.5 2.998,12.848 4.974,12.848 6.985,14.859 11.151,14.859 11.405,14.605 11.405,14.326 v1(11.049,13.97)
MDI_T_P: J3.6 R19.1 | length 12.6
  Top Layer w0.152: v1(12.065,13.97) R19.1
  Bottom Layer w0.152: J3.6 2.998,13.152 4.847,13.152 6.859,15.164 11.277,15.164 11.709,14.731 11.709,14.326 v1(12.065,13.97)
NetC15_1: C15.1 C16.2 U2.28 | length 7.5
  Top Layer w0.229: v1(10.595,17.653) U2.28
  Top Layer w0.381: C15.1 5.715,17.275 v2(7.62,17.275)
  Bottom Layer w0.381: v2(7.62,17.275) 10.217,17.275 v1(10.595,17.653) C16.2
NetLD1_1: LD1.1 R3.2 | length 1.2
  Top Layer w0.152: R3.2 LD1.1
NetLD2_1: LD2.1 R4.1 | length 1.2
  Top Layer w0.152: R4.1 LD2.1
NetLD3_1: LD3.1 R6.1 | length 1.2
  Top Layer w0.152: R6.1 LD3.1
NetLD4_1: LD4.1 R23.1 | length 1.2
  Top Layer w0.152: R23.1 LD4.1
NetLD5_1: LD5.1 R24.1 | length 1.5
  Top Layer w0.152: LD5.1 R24.1@8.898,8.763
NetLD6_1: LD6.1 R25.2 | length 1.5
  Top Layer w0.152: LD6.1 7.408,10.037 R25.2
NetQ1_1: Q1.1 R26.1 | length 10.2
  Bottom Layer w0.152: Q1.1 10.759,4.699 12.827,4.699 13.335,5.207 13.335,8.89 14.101,9.656 R26.1
NetQ1_3: Q1.3 R24.2 | length 5.1
  Top Layer w0.152: R24.2 9.902,8.763 v1(10.795,8.763)
  Bottom Layer w0.152: Q1.3 9.301,5.999 10.795,7.493 v1(10.795,8.763)
NetQ2_1: Q2.1 R27.1 | length 6.3
  Bottom Layer w0.152: Q2.1 13.97,4.1 13.97,8.255 14.351,8.636 14.736,8.636 R27.1@14.867,8.767
NetQ2_3: Q2.3 R25.1 | length 5.6
  Top Layer w0.152: R25.1 9.902,10.033 v1(10.795,10.033)
  Bottom Layer w0.152: v1(10.795,10.033) 12.319,8.509 Q2.3
NetR5_2: R5.2 U1.32 | length 4.1
  Top Layer w0.152: R5.2 24.13,11.049 25.575,12.494 U1.32
NetR10_2: R10.2 U2.25 | length 3.3
  Top Layer w0.152: R10.2 6.858,19.05 7.103,18.805 U2.25
NetR12_2: R12.2 U2.24 | length 2.6
  Top Layer w0.152: R12.2 6.858,20.066 7.369,19.555 U2.24
OUT_RTS: J1.5 U6.6 | length 11.5
  Top Layer w0.152: v1(40.513,7.239) 40.513,7.874 41.021,8.382 v1(43.434,8.382)
  Bottom Layer w0.152: v1(40.513,7.239) 40.529,7.255 U6.6 ; v1(43.434,8.382) 43.942,8.382 44.704,9.144 44.704,10.414 45.339,11.049 46.899,11.049 J1.5
OUT_TXD: J1.4 U6.3 | length 8.4
  Top Layer w0.152: v1(41.783,7.239) v1(43.307,7.239)
  Bottom Layer w0.152: v1(41.783,7.239) 42.029,7.485 U6.3 ; v1(43.307,7.239) 43.434,7.239 45.212,9.017 46.867,9.017 J1.4
PB_04: U1.24 U2.5 | length 22.1
  Top Layer w0.152: U2.5 13.789,21.155 14.859,22.225 14.859,23.622 15.621,24.384 18.161,24.384 19.812,22.733 19.812,18.034 22.152,15.694 U1.24
PB_05: J3.11 R7.2 U1.25 U2.4 | length 37.5
  Top Layer w0.152: J3.11 2.543,24 v1(4.445,22.098) ; U2.4 14.151,20.755 v1(14.478,21.082) 15.24,21.844 15.24,23.495 15.748,24.003 18.034,24.003 19.431,22.606 19.431,17.907 22.044,15.294 U1.25
  Bottom Layer w0.152: v1(4.445,22.098) 4.953,22.606 13.462,22.606 14.478,21.59 v1(14.478,21.082) R7.2
PB_06: U1.16 U2.15 | length 24.2
  Top Layer w0.152: v1(9.652,24.257) 9.795,24.114 U2.15 ; v1(27.432,21.59) 27.432,20.784 27.734,20.482 U1.16
  Bottom Layer w0.152: v1(9.652,24.257) 9.652,25.527 10.033,25.908 16.637,25.908 20.701,21.844 27.178,21.844 v1(27.432,21.59)
PB_07: U1.17 U2.14 | length 27.8
  Top Layer w0.152: U2.14 10.195,24.857 9.779,25.273 9.779,28.448 10.16,28.829 12.827,28.829 14.986,26.67 18.923,26.67 24.511,21.082 24.511,19.177 25.194,18.494 U1.17
PB_09: U1.19 U2.10 | length 22.9
  Top Layer w0.152: U2.10 11.795,23.987 12.446,24.638 13.335,24.638 14.986,26.289 18.796,26.289 21.717,23.368 21.717,18.669 22.692,17.694 U1.19
PB_10: U1.20 U2.9 | length 22.2
  Top Layer w0.152: U2.9 12.195,23.879 12.573,24.257 13.462,24.257 15.113,25.908 18.669,25.908 21.336,23.241 21.336,18.542 22.584,17.294 U1.20
PB_11: U1.21 U2.8 | length 22
  Top Layer w0.152: U2.8 13.465,22.355 13.716,22.606 13.716,24.003 15.24,25.527 18.542,25.527 20.955,23.114 20.955,18.415 22.476,16.894 U1.21
PB_12: U1.22 U2.7 | length 22
  Top Layer w0.152: U2.7 13.573,21.955 14.097,22.479 14.097,23.876 15.367,25.146 18.415,25.146 20.574,22.987 20.574,18.288 22.368,16.494 U1.22
PB_13: U1.23 U2.6 | length 22.1
  Top Layer w0.152: U2.6 13.681,21.555 14.478,22.352 14.478,23.749 15.494,24.765 18.288,24.765 20.193,22.86 20.193,18.161 22.26,16.094 U1.23
PB_14: R11.1 U1.26 U2.23 | length 33
  Top Layer w0.152: R11.1 v1(6.985,21.082) 6.985,20.447 7.477,19.955 U2.23 U2.23@8.596,20.004 ; U1.26 27.467,14.894 27.813,15.24 v1(27.813,16.891)
  Bottom Layer w0.152: v1(6.985,21.082) 6.985,20.447 6.477,19.939 6.477,16.891 7.112,16.256 12.065,16.256 13.081,17.272 25.781,17.272 26.162,16.891 v1(27.813,16.891)
PB_15: U1.27 U2.22 | length 31.4
  Top Layer w0.152: v1(7.62,20.574) 7.839,20.355 U2.22 ; U1.27 27.575,14.494 28.321,15.24 v1(28.321,17.399)
  Bottom Layer w0.152: v1(7.62,20.574) 6.858,19.812 6.858,17.018 7.239,16.637 11.938,16.637 12.954,17.653 26.035,17.653 26.289,17.399 v1(28.321,17.399)
PD_00: U1.11 U2.20 | length 35.9
  Top Layer w0.152: v1(6.35,24.765) 6.35,22.606 7.801,21.155 U2.20 ; U1.11 29.734,20.489 29.972,20.727 v1(29.972,20.955)
  Bottom Layer w0.152: v1(6.35,24.765) 6.35,26.289 7.874,27.813 17.272,27.813 21.336,23.749 28.702,23.749 29.972,22.479 v1(29.972,20.955)
PD_01: U1.12 U2.19 | length 33.8
  Top Layer w0.152: v1(6.858,24.257) 6.858,22.606 7.909,21.555 U2.19 ; U1.12 29.334,20.571 29.464,20.701 v1(29.464,21.59)
  Bottom Layer w0.152: v1(6.858,24.257) 6.858,26.289 8.001,27.432 17.145,27.432 21.209,23.368 28.448,23.368 29.464,22.352 v1(29.464,21.59)
PD_02: U1.13 U2.18 | length 31.7
  Top Layer w0.152: v1(7.366,24.765) 7.366,22.606 8.017,21.955 U2.18 ; U1.13 28.934,20.933 v1(28.956,20.955)
  Bottom Layer w0.152: v1(7.366,24.765) 7.366,26.289 8.128,27.051 17.018,27.051 21.082,22.987 28.194,22.987 28.956,22.225 v1(28.956,20.955)
PD_03: U1.14 U2.17 | length 29.6
  Top Layer w0.152: v1(7.874,24.257) 7.874,22.606 8.125,22.355 U2.17 ; v1(28.448,21.59) 28.448,20.701 28.534,20.615 U1.14
  Bottom Layer w0.152: v1(7.874,24.257) 7.874,26.289 8.255,26.67 16.891,26.67 20.955,22.606 27.94,22.606 28.448,22.098 v1(28.448,21.59)
PD_04: U1.15 U2.16 | length 26.1
  Top Layer w0.152: v1(9.017,24.765) 9.017,24.13 9.395,23.752 U2.16 ; v1(27.94,20.955) 28.134,20.761 U1.15
  Bottom Layer w0.152: v1(9.017,24.765) 9.017,25.908 9.398,26.289 16.764,26.289 20.828,22.225 27.559,22.225 27.94,21.844 v1(27.94,20.955)
PHY_AD0: J3.8 R9.2 U1.29 U2.11 | length 53.3
  Top Layer w0.152: U2.11 11.395,24.095 12.446,25.146 v1(12.446,25.4) R9.2 ; U1.29 27.308,13.694 28.829,15.215 v1(28.829,16.891)
  Bottom Layer w0.152: v1(12.446,25.4) 12.446,23.495 11.938,22.987 4.445,22.987 3.683,22.225 3.683,18.288 3.395,18 J3.8 2.67,17.48 5.38,17.48 6.985,15.875 12.192,15.875 13.208,16.891 25.527,16.891 26.035,16.383 28.321,16.383 v1(28.829,16.891)
PHY_AD3: J3.10 R8.2 U2.12 | length 14.8
  Top Layer w0.152: U2.12 10.995,24.203 11.43,24.638 v1(11.43,25.404) R8.2
  Bottom Layer w0.152: J3.10 2.823,22 4.191,23.368 10.922,23.368 11.43,23.876 v1(11.43,25.404)
RESETN: R18.1 U1.28 U2.32 U3.3 U4.4 | length 38.8
  Top Layer w0.152: U2.32 14.342,18.805 15.367,17.78 v1(15.367,11.811) v1(15.367,5.588) ; v1(21.971,11.819) 24.392,11.819 25.146,12.573 25.146,13.716 25.524,14.094 U1.28
  Bottom Layer w0.152: v1(15.367,5.588) 21.473,5.588 U3.3@21.6,5.715 ; v1(15.367,11.811) 17.221,11.811 17.229,11.819 v1(21.971,11.819) 22.167,11.623 U4.4 ; v1@21.979,11.819 R18.1
SCL1: R16.1 U1.57 U5.1 | length 16.5
  Top Layer w0.152: U1.57 36.503,15.694 36.703,15.494 36.703,9.525 39.565,6.663 39.565,4.768 U5.1 v1(38.489,4.76)
  Bottom Layer w0.152: v1(38.489,4.76) 40.082,4.76 R16.1
SDA1: R15.1 U1.58 U5.3 | length 20.3
  Top Layer w0.152: U1.58 36.611,16.094 37.084,15.621 37.084,9.652 40.64,6.096 40.64,3.04 40.46,2.86 U5.3 v1(38.489,2.86)
  Bottom Layer w0.152: v1(38.489,2.86) 40.082,2.86 R15.1
SPI_MISO1: U1.47 U3.8 | length 14.5
  Top Layer w0.152: U1.47 33.334,9.712 33.274,9.652 33.274,9.271 v1(33.782,8.763)
  Bottom Layer w0.152: U3.8 28.321,3.048 27.813,3.556 27.813,7.112 28.321,7.62 32.639,7.62 v1(33.782,8.763)
SPI_MOSI1: U1.48 U3.1 | length 18.9
  Top Layer w0.152: U1.48 33.734,9.573 v1(33.782,9.525)
  Bottom Layer w0.152: U3.1 23.749,3.048 24.257,3.556 24.257,7.366 24.257,7.493 24.892,8.128 32.385,8.128 v1(33.782,9.525)
SPI_SCLK1: U1.46 U3.2 | length 16.6
  Top Layer w0.152: v1(32.766,9.525) 32.934,9.693 U1.46
  Bottom Layer w0.152: U3.2 23.368,4.318 23.876,4.826 23.876,7.493 ; 23.876,7.62 24.765,8.509 31.75,8.509 v1(32.766,9.525)
SPI_SSEL1: R13.1 U1.45 U3.4 | length 17.7
  Top Layer w0.152: v1(32.258,10.033) 32.534,10.309 U1.45 32.534,14.845 v1(32.52,14.859)
  Bottom Layer w0.152: U3.4 22.606,6.858 23.368,7.62 24.638,8.89 31.369,8.89 32.258,9.779 v1(32.258,10.033) ; v1(32.52,14.859) R13.1
STATUS: J1.12 LD4.2 U1.35 | length 42.5
  Top Layer w0.152: v1(29.972,14.478) 29.464,14.478 28.534,13.548 U1.35 28.534,9.693 30.861,7.366 36.068,7.366 36.36,7.074 LD4.2
  Bottom Layer w0.152: v1(29.972,14.478) 31.922,14.478 32.303,14.097 39.497,14.097 42.545,17.145 42.545,24.511 43.034,25 46.85,25 J1.12
STATUS_LED0: J2.2 LD2.2 U1.1 | length 38.9
  Top Layer w0.152: U1.1 33.734,20.653 34.036,20.955 35.941,20.955 37.338,22.352 42.164,22.352 42.545,21.971 42.545,12.319 44.323,10.541 44.323,7.239 45.562,6 J2.2 ; LD2.2 v1(37.338,3.683)
  Bottom Layer w0.152: v1(37.338,3.683) 37.846,4.191 37.846,5.08 38.258,5.492 J2.2@45.85,5.492
STATUS_LED1: J2.3 LD3.2 U1.2 | length 38
  Top Layer w0.152: U1.2 33.334,20.761 33.909,21.336 35.814,21.336 37.211,22.733 42.291,22.733 42.926,22.098 42.926,12.446 44.704,10.668 44.704,9.017 45.721,8 J2.3 ; LD3.2 v1(37.338,5.08)
  Bottom Layer w0.152: v1(37.338,5.08) 37.338,5.461 37.719,5.842 43.692,5.842 J2.3
SWCLK: J4.3 U1.49 | length 14.5
  Top Layer w0.152: v1(32.258,17.399) 32.258,16.002 33.274,14.986 33.274,13.081 33.861,12.494 U1.49
  Bottom Layer w0.152: J4.3 31.115,22.606 32.258,21.463 v1(32.258,17.399)
SWDIO: J4.2 U1.50 | length 13.5
  Top Layer w0.152: v1(32.766,17.907) 32.766,16.002 33.655,15.113 33.655,13.208 33.969,12.894 U1.50
  Bottom Layer w0.152: J4.2 32.385,21.971 32.766,21.59 v1(32.766,17.907)
U_CTS0: U1.40 U6.11 | length 13.6
  Top Layer w0.152: U1.40 v1(30.534,12.573)
  Bottom Layer w0.152: v1(30.534,12.573) 31.121,13.16 32.083,13.16 41.196,13.16 41.529,12.827 U6.11@41.529,11.86
U_DSR0: J1.10 U1.37 | length 26.1
  Top Layer w0.152: U1.37 29.334,12.443 v1(29.464,12.573)
  Bottom Layer w0.152: v1(29.464,12.573) 29.464,13.081 29.845,13.462 30.995,13.462 32.208,13.462 39.243,13.462 39.878,13.462 43.307,16.891 43.307,20.619 43.688,21 46.85,21 J1.10
U_DTR0: J1.6 U1.38 | length 25.2
  Top Layer w0.152: v1(29.591,10.033) 29.734,10.176 U1.38 ; v1(39.624,8.128) 40.259,8.763 42.418,8.763 v1(43.688,10.033)
  Bottom Layer w0.152: v1(29.591,10.033) 29.591,10.922 30.02,11.351 35.224,11.351 38.447,8.128 v1(39.624,8.128) ; v1(43.688,10.033) 44.704,11.049 44.704,12.446 45.212,12.954 46.804,12.954 J1.6
U_RTS0: U1.41 U6.5 | length 17.3
  Top Layer w0.152: v1(30.734,10.033) 30.934,10.233 U1.41
  Bottom Layer w0.152: v1(30.734,10.033) 30.734,10.668 31.066,11 35.101,11 35.814,10.287 35.814,7.62 36.83,6.604 40.767,6.604 41.029,6.866 U6.5
U_RXD0: R26.2 U1.43 U6.8 | length 27.2
  Top Layer w0.152: U1.43 v1(31.734,12.573)
  Bottom Layer w0.152: R26.2 15.871,9.652 27.686,9.652 29.845,11.811 30.972,11.811 v1(31.734,12.573) 32.004,12.573 32.766,11.811 37.465,11.811 38.493,10.783 U6.8
U_RXD2: J2.6 J5.4 U1.4 | length 32.2
  Top Layer w0.152: U1.4 32.534,20.977 33.655,22.098 35.56,22.098 37.211,23.749 v1(39.497,23.749) 42.291,23.749 43.688,22.352 43.688,14.605 44.293,14 J2.6
  Bottom Layer w0.152: J5.4 36.957,24.638 39.116,24.638 39.497,24.257 v1(39.497,23.749)
U_TXD0: R27.2 U1.42 U6.2 | length 34.5
  Top Layer w0.152: U1.42 31.334,10.195 v1(31.496,10.033)
  Bottom Layer w0.152: R27.2@15.867,8.767 15.998,8.636 23.622,8.636 24.257,9.271 31.115,9.271 31.496,9.652 v1(31.496,10.033) 31.496,10.414 31.75,10.668 34.925,10.668 35.433,10.16 35.433,7.493 36.703,6.223 41.91,6.223 42.529,6.842 U6.2
U_TXD2: J2.5 J5.3 U1.3 | length 33.1
  Top Layer w0.152: U1.3 32.934,20.869 33.782,21.717 35.687,21.717 37.211,23.241 v1(40.005,23.241) 42.291,23.241 43.307,22.225 43.307,12.573 43.88,12 J2.5
  Bottom Layer w0.152: J5.3 36.195,25.908 37.084,25.019 39.624,25.019 40.005,24.638 v1(40.005,23.241)
VCC_3.3V: C1.1 C2.2 C5.1 C6.2 C13.2 C17.1 C18.2 C19.2 C21.1 J1.1 J3.12 J4.1 J5.1 L2.1 Q1.2 Q2.2 R3.1 R4.2 R6.2 R13.2 R14.2 R15.2 R16.2 R23.2 R28.2 U1.10 U1.61 U3.5 U3.6 U4.5 U5.4 U6.14 | length 34.4
  Top Layer w0.203: v1(29.853,18.415) 30.134,18.696 U1.10
  Top Layer w0.229: v1(33.655,16.899) 34.05,17.294 U1.61
  Top Layer w0.381: v1(22.479,21.082) 22.479,20.189 R28.2 ; C18.2 22.987,14.597 R14.2 23.834,13.581 v2(23.884,13.531) ; v2(31.623,6.215) 31.885,6.477 R23.2 ; v1(31.75,2.286) R3.1 ; v1(31.75,3.683) R4.2 ; v1(31.75,5.08) R6.2 ; U5.4 v1(42.807,2.86)
  Top Layer w0.508: C1.1 v2(38.735,14.986)
  Bottom Layer w0.152: U6.14 43.93,10.783 44.196,11.049 v1(44.196,12.7) 44.196,13.069 C21.1
  Bottom Layer w0.381: Q1.2 7.559,2.093 8.128,1.524 v2(9.398,1.524) 10.795,1.524 11.369,2.098 Q2.2 ; v2@23.884,13.523 U4.5 ; U3.6 30.099,5.588 30.226,5.461 30.726,5.461 C17.1 ; U3.5 30.353,6.858 30.734,6.477 C17.1 ; v1(29.853,18.415) C6.2 ; v2(31.623,6.215) 31.623,5.969 31.107,5.453 C17.1 ; R13.2 v1(33.52,16.129) ; v1(33.655,16.899) C2.2 ; R16.2 C19.2 R15.2 42.045,2.794 42.111,2.86 v1(42.807,2.86)
  other v2: 26.67,24.638 26.67,25.654
XIN: C4.2 R1.2 U1.63 Y1.3 | length 8.6
  Top Layer w0.152: U1.63 36.001,18.094 37.092,19.185 R1.2 40.505,19.185 40.755,18.935 Y1.3 40.505,17.877 C4.2
XOUT: C3.2 R1.1 U1.64 Y1.1 | length 6.5
  Top Layer w0.152: U1.64 35.893,18.494 37.584,20.185 R1.1 39.213,20.185 Y1.1 39.505,20.477 C3.2
XTAL1: C7.2 U2.2 Y2.1 | length 7.6
  Top Layer w0.152: U2.2 17.637,19.955 17.895,19.697 Y2.1 17.645,18.889 C7.2
XTAL2: C8.2 U2.3 Y2.3 | length 5.8
  Top Layer w0.152: U2.3 16.395,20.355 Y2.3 16.645,20.989 C8.2
pads on no net: J3.1 J3.9 U1.30 U1.31 U1.33 U1.34 U1.44 U1.51 U1.52 U1.53 U1.54 U1.55 U1.56 U1.59 U1.60 U2.1 U2.21 U4.1

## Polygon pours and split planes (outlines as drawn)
GND on Top Layer "Top Layer-net" (solid, remove dead copper, pour order 10): 0.889,30 0,30 0,26.289 0,0 45.466,0 50,0 50,5.207 50,30 1.016,30
IP_3.3V on Top Layer "Top Layer-NET" (solid, remove dead copper, pour order 14): 24.003,26.162 24.257,25.908 24.257,24.384 24.003,24.13 21.844,24.13 21.59,24.384 21.59,25.908 21.844,26.162 23.368,26.162
VCC_3.3V on Top Layer "Top Layer-NET" (solid, remove dead copper, pour order 20): 24.765,26.162 24.511,25.908 24.511,24.384 24.765,24.13 26.924,24.13 27.178,24.384 27.178,25.908 26.924,26.162
GND on Bottom Layer "Top Layer-net" (solid, remove dead copper, pour order 12): 1.778,30 0,30 0,27.813 0,0 5.461,0 50,0 50,4.318 50,30 1.905,30
IP_3.3V on Bottom Layer "Top Layer-NET" (solid, remove dead copper, pour order 16): 23.749,26.289 21.844,26.289 21.59,26.035 21.59,24.384 21.844,24.13 23.749,24.13 24.003,24.384 24.003,26.035
VCC_3.3V on Bottom Layer "Top Layer-NET" (solid, remove dead copper, pour order 18): 25.781,26.289 25.019,26.289 24.765,26.035 24.765,24.384 25.019,24.13 26.924,24.13 27.178,24.384 27.178,26.035 26.924,26.289
GND on Internal Plane 1 (split plane): 49.304,29.483 49.365,29.458 49.417,29.417 49.458,29.365 49.483,29.304 49.49,29.247 49.49,29.238 49.49,0.762 49.49,0.753 49.483,0.696 49.458,0.635 49.417,0.583 49.365,0.542 49.304,0.517 49.247,0.51 49.238,0.51 0.762,0.51 0.753,0.51 0.696,0.517 0.635,0.542 0.583,0.583 0.542,0.635 0.517,0.696 0.51,0.753 0.51,0.762 0.51,29.238 0.51,29.247 0.517,29.304 0.542,29.365 0.583,29.417 0.635,29.458 0.696,29.483 0.753,29.49 0.762,29.49 49.238,29.49 49.247,29.49
IP_3.3V on Internal Plane 2 (split plane): 24.128,28.102 22.835,28.102 22.835,24.105 24.128,24.105 24.128,22.989 20.32,22.989 20.254,22.98 20.192,22.955 20.139,22.914 20.098,22.861 20.073,22.799 20.064,22.733 20.064,13.464 3.939,13.464 3.939,29.49 24.128,29.49
VCC_3.3V on Internal Plane 2 (split plane): 49.304,29.483 49.365,29.458 49.417,29.417 49.458,29.365 49.483,29.304 49.49,29.247 49.49,29.238 49.49,0.762 49.49,0.753 49.483,0.696 49.458,0.635 49.417,0.583 49.365,0.542 49.304,0.517 49.247,0.51 49.238,0.51 0.762,0.51 0.753,0.51 0.696,0.517 0.635,0.542 0.583,0.583 0.542,0.635 0.517,0.696 0.51,0.753 0.51,0.762 0.51,29.238 0.51,29.247 0.517,29.304 0.542,29.365 0.583,29.417 0.635,29.458 0.696,29.483 0.753,29.49 0.762,29.49 3.427,29.49 3.427,13.208 3.436,13.142 3.461,13.08 3.502,13.027 3.555,12.986 3.617,12.961 3.683,12.952 20.32,12.952 20.386,12.961 20.448,12.986 20.501,13.027 20.542,13.08 20.567,13.142 20.576,13.208 20.576,22.477 24.384,22.477 24.45,22.486 24.512,22.511 24.565,22.552 24.606,22.605 24.631,22.667 24.64,22.733 24.64,24.105 25.933,24.105 25.933,29.459 24.64,29.459 24.64,29.49 49.238,29.49 49.247,29.49

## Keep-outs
Keep-Out Layer:
  the board outline again, w0.127
  text ".Layer_Name" at 9.398,31.75 h1.52

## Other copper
Top Layer:
  pour cut-out: 13.25,14.8 13.75,14.8 13.6,14.65 13.6,14.375 13.25,14.375
  pour cut-out: 21.425,11.85 21.339,11.85 21.339,11.936 21.122,12.153 21.425,12.153
  pour cut-out: 23.788,10.661 23.572,10.445 23.572,10.661
  pour cut-out: 43.025,9.975 43.025,10.3 43.025,11.175 43.025,11.275 43.45,11.275 43.45,9.975
  pour cut-out: 39.975,12.85 39.975,12.4 39.8,12.4 39.675,12.275 39.675,12.4 39.675,12.95 39.775,12.85
  pour cut-out: 41.875,13.35 42.125,13.1 42.275,13.1 42.275,13.35
  pour cut-out: 2.65,23.1 3.075,23.1 3.775,22.375 3.581,22.319 3.525,22.375 3.25,22.375 3.175,22.3 2.65,22.4
  pour cut-out: 10.175,29.625 10.3,29.5 10.3,29.325 10.2,29.225 10.275,29.225 12.825,29.225 12.75,29.3 12.75,29.5 12.875,29.625
  pour cut-out: 36.275,16.45 35.975,16.75 35.975,16.45
  pour cut-out: 35.95,17.475 36.2,17.725 35.95,17.725
  pour cut-out: 28.125,10 27.913,10.213 28.125,10.213
  pour cut-out: 27.278,11.822 27.062,12.038 27.278,12.038
  pour cut-out: 27.275,18.937 27.062,18.937 27.275,19.15
  pour cut-out: 13.675,19.15 13.675,19.6 14.475,19.6 14.325,19.45 14.325,19.3 14.475,19.15
  pour cut-out: 18.25,17.725 18.375,17.85 18.25,17.85
  pour cut-out: 16.1,22 16.1,22.35 15.925,22.175 15.75,22.175 15.625,22.3 15.625,22
  pour cut-out: 20.7,0.35 20.875,0.525 20.875,0.775 20.775,0.875 20.925,0.875 49.725,0.875 49.725,0.35
  pour cut-out: 40.9,6.425 40.9,6.65 41,6.75 41.475,6.75 41.475,6.975 40.9,6.975 40.6,6.975 40.6,6.425
  pour cut-out: 43.75,6.825 43.775,6.825 43.85,6.85 44.025,6.85 44.15,6.825 44.15,6.95 43.75,6.95
  pour cut-out: 44.8,6.05 44.8,6.175 44.75,6.175 44.771,6.05
  pour cut-out: 41.35,3.425 41.025,3.75 41.025,3.425
  pour cut-out: 22.875,21.425 22.875,21.525 23.175,21.825 23.302,21.825 23.325,21.675 23.152,21.675 23.026,21.549 22.975,21.425
  pour cut-out: 27.575,24.765 ccw(c28.575,24.765) 28.575,23.765 ccw(c28.575,24.765) 29.575,24.765 ccw(c28.575,24.765) 28.575,25.765 ccw(c28.575,24.765)
  pour cut-out: 27.575,27.94 ccw(c28.575,27.94) 28.575,26.94 ccw(c28.575,27.94) 29.575,27.94 ccw(c28.575,27.94) 28.575,28.94 ccw(c28.575,27.94)
  pour cut-out: 1.15,16 ccw(c2.15,16) 2.15,15 ccw(c2.15,16) 3.15,16 ccw(c2.15,16) 2.15,17 ccw(c2.15,16)
  pour cut-out: 1.15,10 ccw(c2.15,10) 2.15,9 ccw(c2.15,10) 3.15,10 ccw(c2.15,10) 2.15,11 ccw(c2.15,10)
  pour cut-out: 44.85,26 ccw(c45.85,26) 45.85,25 ccw(c45.85,26) 46.85,26 ccw(c45.85,26) 45.85,27 ccw(c45.85,26)
  pour cut-out: 46.85,24 ccw(c47.85,24) 47.85,23 ccw(c47.85,24) 48.85,24 ccw(c47.85,24) 47.85,25 ccw(c47.85,24)
  pour cut-out: 46.85,16 ccw(c47.85,16) 47.85,15 ccw(c47.85,16) 48.85,16 ccw(c47.85,16) 47.85,17 ccw(c47.85,16)
  pour cut-out: 46.85,8 ccw(c47.85,8) 47.85,7 ccw(c47.85,8) 48.85,8 ccw(c47.85,8) 47.85,9 ccw(c47.85,8)
  pour cut-out: 44.85,4 ccw(c45.85,4) 45.85,3 ccw(c45.85,4) 46.85,4 ccw(c45.85,4) 45.85,5 ccw(c45.85,4)
  text ".Layer_Name" at 9.398,31.75 h1.52
Bottom Layer:
  pour cut-out: 28.15,11.925 29,11.925 29.075,11.85 29.075,11.625 29.1,11.6 29.425,11.6 29.425,12.4 28.15,12.4
  region net GND: 40.132,9.144 40.005,9.144 39.37,9.144 39.243,9.017 38.481,9.017 38.354,9.144 38.354,9.652 38.481,9.779 38.989,9.779 39.37,9.398 40.132,9.398
  pour cut-out: 39.243,8.6 39.243,8.89 39.578,9.225 40.533,9.225 40.332,8.6
  pour cut-out: 42.65,9.2 43.675,9.2 43.725,9.25 43.725,9.35 43.675,9.4 43.225,9.4 43.225,9.625 43.675,9.625 44.3,9.625 44.3,9.2 44.3,8.875 42.65,8.875
  pour cut-out: 42.525,10.4 43.35,10.4 43.35,9.575 43.257,9.575 43.225,9.575 43.2,9.6 43.175,9.625 43.15,9.65 43.075,9.725 43.025,9.775 43.025,10.2 42.975,10.25 42.525,10.25
  pour cut-out: 44.95,13.962 44.761,14 44.766,13.962 44.55,13.962 44.55,13.125 44.95,13.125
  pour cut-out: 37.6,3.15 37.6,3.125 37.675,3.125 37.85,3.125 38,2.975 38.489,3.507 38.368,3.507 38.2,3.675 38.2,3.9 38.4,4.1 38.675,4.1 38.8,4.225 38.2,4.225 38.2,4.075 37.6,3.425
  pour cut-out: 27.225,24.1 27.225,25.625 27.45,25.4 27.9,25.4 28,25.5 28,24.1
  pour cut-out: 14.95,5.15 14.75,5.35 14.475,5.35 14.325,5.2 14.325,6 14.475,5.85 14.8,5.85 14.95,6
  pour cut-out: 41.725,4.875 41.95,5.1 41.725,5.1
  pour cut-out: 32.2,6.7 32,6.9 32,7.1 32.275,7.375 30.9,7.375 30.9,6.7
  pour cut-out: 34.025,10.25 35.075,10.25 35.075,8.15 34.85,8.375 34.3,8.375 34.225,8.3 34.025,8.3
  pour cut-out: 9.362,10.75 9.687,10.75 9.687,10.9 9.362,10.9
  pour cut-out: 10.275,10.339 10.275,10.525 10.125,10.675 10.075,10.7 10.075,10.725 10.3,10.95 10.4,10.95 10.425,10.85 10.6,10.675 10.704,10.646
  pour cut-out: 42.4,13.025 42.4,13.65 42.2,13.65 42.2,13.025
  pour cut-out: 32.025,2.75 32.025,4.75 31.45,4.75 31.45,2.75
  pour cut-out: 34.15,14.9 34.15,14.625 34.225,14.55 34.375,14.55 34.375,14.45 34.075,14.45 34.075,14.9
  pour cut-out: 4.075,23.75 3.925,23.5 3.025,23.65 3,23.65 3,24 3.3,23.7 3.675,23.625
  pour cut-out: 12.925,22.95 13.028,22.95 13.028,23.053 12.925,23.156 12.925,25.075 12.675,25.075 12.675,22.95
  pour cut-out: 6.1,23.75 6.225,23.875 6.225,24.1 6.1,24.225 6.4,24.225 6.4,23.75
  pour cut-out: 6.475,15.325 6.475,15.8 6.75,15.8 6.75,15.325
  pour cut-out: 29.575,24.765 cw(c28.575,24.765) 28.575,23.765 cw(c28.575,24.765) 27.575,24.765 cw(c28.575,24.765) 28.575,25.765 cw(c28.575,24.765)
  pour cut-out: 29.575,27.94 cw(c28.575,27.94) 28.575,26.94 cw(c28.575,27.94) 27.575,27.94 cw(c28.575,27.94) 28.575,28.94 cw(c28.575,27.94)
  pour cut-out: 3.15,16 cw(c2.15,16) 2.15,15 cw(c2.15,16) 1.15,16 cw(c2.15,16) 2.15,17 cw(c2.15,16)
  pour cut-out: 3.15,10 cw(c2.15,10) 2.15,9 cw(c2.15,10) 1.15,10 cw(c2.15,10) 2.15,11 cw(c2.15,10)
  pour cut-out: 46.85,26 cw(c45.85,26) 45.85,25 cw(c45.85,26) 44.85,26 cw(c45.85,26) 45.85,27 cw(c45.85,26)
  pour cut-out: 48.85,24 cw(c47.85,24) 47.85,23 cw(c47.85,24) 46.85,24 cw(c47.85,24) 47.85,25 cw(c47.85,24)
  pour cut-out: 48.85,16 cw(c47.85,16) 47.85,15 cw(c47.85,16) 46.85,16 cw(c47.85,16) 47.85,17 cw(c47.85,16)
  pour cut-out: 48.85,8 cw(c47.85,8) 47.85,7 cw(c47.85,8) 46.85,8 cw(c47.85,8) 47.85,9 cw(c47.85,8)
  pour cut-out: 46.85,4 cw(c45.85,4) 45.85,3 cw(c45.85,4) 44.85,4 cw(c45.85,4) 45.85,5 cw(c45.85,4)
  text ".Layer_Name" at 9.398,31.75 h1.52
Internal Plane 1 (plane layer: these items are gaps in the copper):
  pour cut-out: 21.7,24.9 21.7,25.35 21.725,25.35 22.475,25.35 22.475,24.9
  pour cut-out: 26.25,24.9 26.25,25.35 26.275,25.35 27.025,25.35 27.025,24.9
  text "GND" at 9.398,31.782 h1.52
Internal Plane 2 (plane layer: these items are gaps in the copper):
  pour cut-out: 9.9,21.85 9.9,20.075 11.725,20.075 11.725,21.85
  pour cut-out: 14.55,12.075 15.175,12.075 15.175,11.475 14.55,11.475
  lines w0.508: 3.683,30 3.683,13.208 20.32,13.208 20.32,22.733 24.384,22.733 24.384,30
  text "POWER" at 9.398,31.782 h1.52
  text "IP_3.3V" at 23.749,24.257 h0.76 r90
  text "VCC_3.3V" at 25.527,24.257 h0.76 r90

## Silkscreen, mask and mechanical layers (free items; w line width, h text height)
Top Overlay:
  rectangle: 3.4,0.325 29.4,7.325
  lines w0.127: 49.492,-0.009 ccw(c49.511,0.264) 49.784,0.254 ; 0.127,0.254 ccw(c0.381,0.254) 0.381,0 49.53,0 49.657,0.127 ; 0.127,0.254 0.254,0.127 49.657,0.127 ; 0.127,0.254 49.784,0.254 ; 49.657,0.127 49.784,0.254
  text ".Layer_Name" at 9.398,31.782 h1.52
  text "JTAG" at 34.544,23.876 h1.27
  text "W7500" at 29.083,22.352 h1.27
  text "10" at 43.434,21.717 h0.64
  text "9" at 3.556,19.685 h0.64
  text "5" at 3.556,11.684 h0.64
  text "5" at 43.942,11.684 h0.64
  text "UART0" at 5.08,10.846 h1.27
  text "Tx" at 3.683,9.652 h1.27
  text "Rx" at 3.683,8.433 h1.27
  text "WIZ750SR-100 Ver1.0" at 16.15,7.6 h1.52
Bottom Overlay:
  lines w0.2: 6.121,28.067 17.272,28.067 ; 7.747,25.527 17.272,25.527 ; 7.874,26.797 17.272,26.797
  text ".Layer_Name" at 9.398,31.75 h1.52
  text "5" at 30.799,29.074 h0.64 r270
  text "WIZ750SR-100" at 17.272,28.321 h1.2
  text "http://wizwiki.net" at 17.272,27.178 h1
  text "GND" at 29.337,26.035 h0.64
  text "RSTN" at 32.131,26.035 h0.64
  text "RXD" at 34.417,26.035 h0.64
  text "TXD" at 36.957,26.035 h0.64
  text "BOOT" at 39.751,26.035 h0.64
  text "3.3V" at 42.291,26.035 h0.64
  text "Designed by WIZnet" at 17.272,25.908 h1
  text "10" at 44.323,21.717 h0.64
  text "10" at 4.445,21.59 h0.64
  text "5" at 4.064,11.684 h0.64
  text "5" at 44.323,11.684 h0.64
  text "1" at 3.81,3.683 h0.64
  text "1" at 44.204,3.048 h0.64
Top Paste:
  text ".Layer_Name" at 9.398,31.75 h1.52
Bottom Paste:
  text ".Layer_Name" at 9.398,31.75 h1.52
Top Solder:
  text ".Layer_Name" at 9.398,31.75 h1.52
Bottom Solder:
  text ".Layer_Name" at 9.398,31.75 h1.52
Drill Guide:
  text ".Layer_Name" at 9.398,31.75 h1.52
Mechanical 2:
  lines w0.127: 54.432,12.065 80.594,12.065 ; 54.432,14.859 80.594,14.859 ; 0,0.762 ccw(c0.762,0.762) 0.762,0 49.238,0 ccw(c49.238,0.762) 50,0.762 50,29.238 ccw(c49.238,29.238) 49.238,30 0.762,30 ccw(c0.762,29.238) 0,29.238 0,0.762 ; 53.086,0.711 ccw(c53.797,0.711) 53.797,0 80.975,0 ccw(c80.975,0.711) 81.686,0.711 81.686,19.939 ccw(c80.975,19.939) 80.975,20.65 53.797,20.65 ccw(c53.797,19.939) 53.086,19.939 53.086,0.711
  text "BOARD NAME : WIZ750SR-100" at 0,42.926 h1.52
  text "VERSION : V1.0" at 0,40.132 h1.52
  text "SIZE : 50mmX30mmX1.6T" at 0,37.338 h1.52
  text "GERBER DATE : 2017.12.15" at 0,34.544 h1.52
  text "LAYER :" at 0,31.75 h1.52
  text "Layer Stack Up Detail for:" at 54.559,18.542 h1.02
  text "WIZ750SR-100 V1.0.PcbDoc" at 54.432,16.129 h1.27
  text "Layer Name : 4L  1.6T" at 54.559,12.954 h1.02
  text "Top Layer" at 54.432,9.271 h1.52
  text "GND" at 54.432,6.477 h1.52
  text "POWER" at 54.432,3.81 h1.52
  text "Bottom Layer" at 54.432,1.27 h1.52
  text "KS Technology artwork" at 53.086,-4.064 h5.08
Drill Drawing:
  text ".Layer_Name" at 9.398,31.75 h1.52
  text ".Legend" at 55.118,23.368 h1.02

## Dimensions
0.762,0 to 0.762,30 on Mechanical 2
0,0.762 to 50,0.762 on Mechanical 2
